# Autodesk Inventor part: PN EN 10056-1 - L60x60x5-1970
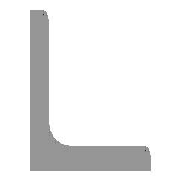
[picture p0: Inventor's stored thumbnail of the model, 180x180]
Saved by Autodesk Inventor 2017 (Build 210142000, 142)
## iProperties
Created: 2016-02
Part Number: PN EN 10056-1 - L60x60x5-1970
Material: Stal, miękka
Description: Kątownik równoramienny
Document SubType Name: Modeling
Standard: PN
Designer: X
Standards Organization: PN
Language: pl-PL
Size Designation: L60x60x5
Categories: <MemberInstance><Categories><Category DisplayName="Kształtowniki konstrukcyjne" InternalName="089c4875-fa83-4c05-b084-43b9cc11f5ed" Mnemonic="GRDR"><CategoryPar
Stock Number: L60x60x5
Density: 7.85 g/cm^3
Appearance: Częściowo polerowana
G_W: 60,000 mm
G_H: 60,000 mm
G_L: 1970,000 mm
IsCustomPart: 1
_CCFamilyMember: 130
_CCFamilyDisplayName: PN EN 10056-1 (Kątownik równoramienny) - Kątownik równoramienny
_FrameMemberDoc: Frame Member File
_Version: 15.0.0
_GetPNFromCC: 1
Author: X
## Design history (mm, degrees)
node "Płaszczyzna początkowa"
node "Płaszczyzna końcowa"
sketch "Szkic"
  geometry: L1 (-11.517, -3.517)-(-11.517, 39.483); L2 (-16.517, 43.483)-(-15.517, 43.483); L3 (-16.517, -16.517)-(-16.517, 43.483); L4 (-16.517, -16.517)-(43.483, -16.517); L5 (43.483, -15.517)-(43.483, -16.517); L6 (-3.517, -11.517)-(39.483, -11.517); L7 (0, 56.477)-(0, -28.683) reference; L8 (-28.683, 0)-(56.477, 0) reference; A1 r 8 centre (-3.517, -3.517) between (-11.517, -3.517) and (-3.517, -11.517); A2 r 4 centre (-15.517, 39.483) between (-11.517, 39.483) and (-15.517, 43.483); A3 r 4 centre (39.483, -15.517) between (43.483, -15.517) and (39.483, -11.517); 3 further points
  constraints: 12 end point, 6 point on circle, 6 point on line, 6 tangent, 3 centre point, 3 horizontal, 3 vertical, 1 equal radius
  dimensions: "d4" = 60 distance of L3.start L4.end (= b); "d6" = 60 distance of L3.start L2.start (= b); "d8" = 5 distance of point (43.483, -11.517) L4.end (= ParT); "d10" = 5 distance of L2.start point (-11.517, 43.483) (= ParT); "d17" = 8 radius of A1 (= R); "d18" = 4 radius of A2 (= R1); "d19" = 16.51748 distance between parallel lines of L8 L4 (= ex); "d20" = 16.51748 distance between parallel lines of L3 L7 (= d19)
extrude "Bryła" new body sketch "Szkic" stored distance "d11" = 1970 (= G_L); taper "d12" = 0 deg
node "Driven Length"
  sketch "Sketch3"
    geometry: L1 (0, 0)-(10, 0) reference
    constraints: 2 end point, 1 horizontal
  workplane "Work Plane10"
  sketch "Sketch4"
    geometry: L1 (-2, 0)-(12, 0) reference; L2 (-2, 1970)-(12, 1970) reference
    dimensions: "d24" = 1970 distance between parallel lines of L1 L2 (derived)
body "Solid1"
other parameters: "b" = 60 [user parameter; used in 3 equation terms], "ParT" = 5 [user parameter; used in 3 equation terms], "R" = 8 [user parameter; used in 1 equation term], "R1" = 4 [user parameter; used in 1 equation term], "G_L" = 1970 (= d24) [user parameter; used in 1 equation term], "d7" = 4 (derived), "d9" = 4 (derived), "ex" = 16.51748 (computed from b, ParT) [user parameter; used in 1 equation term], "G_OFFSET_START" = 0 [user parameter; used in 1 equation term], "G_OFFSET_END" = 0 [user parameter; used in 1 equation term], "d21" = 0 (computed from G_OFFSET_START), "d23" = 90 deg
